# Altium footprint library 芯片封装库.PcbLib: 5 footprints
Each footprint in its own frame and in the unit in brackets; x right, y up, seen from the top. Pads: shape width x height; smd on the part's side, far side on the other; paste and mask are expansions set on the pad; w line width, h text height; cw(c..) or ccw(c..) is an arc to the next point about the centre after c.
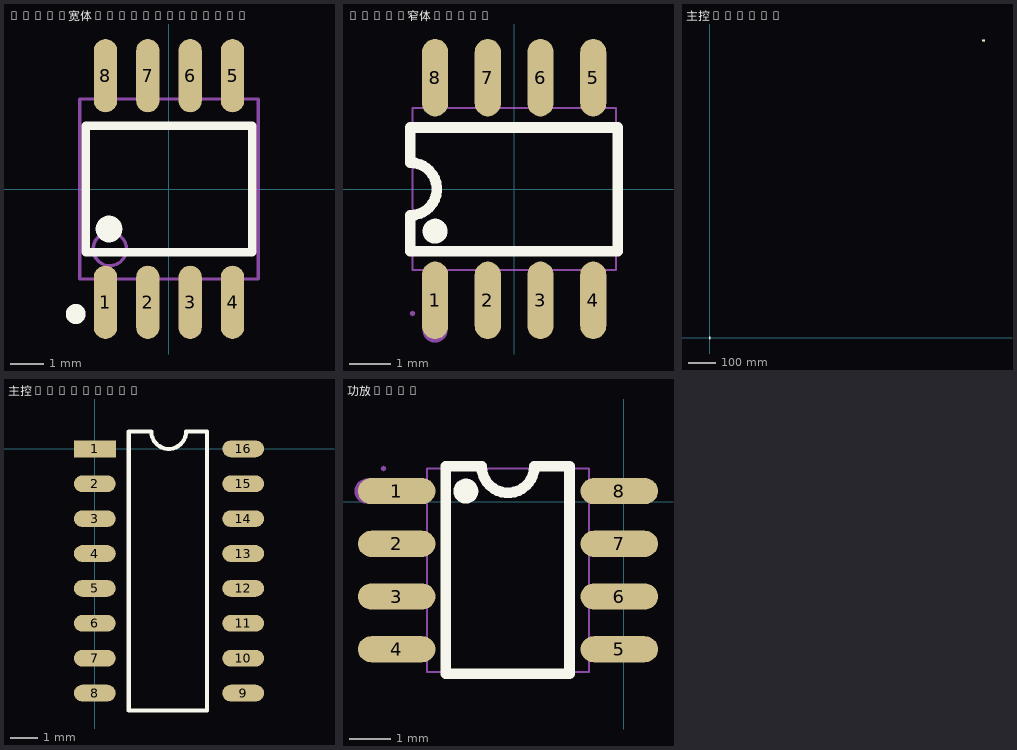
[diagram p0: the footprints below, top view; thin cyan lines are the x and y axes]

## flash宽体SOIC-8_208mil [mm]
height 5.33
pads (8):
  oval 0.7x2.2 smd: 1(-1.905,-3.4) 2(-0.635,-3.4) 3(0.635,-3.4) 4(1.905,-3.4) 5(1.905,3.4) 6(0.635,3.4) 7(-0.635,3.4) 8(-1.905,3.4)
Top Overlay:
  circle w0.4: c-1.8,-1.2 r0.2
  circle w0.3: c-2.797,-3.75 r0.15
  lines w0.254: -2.5,-1.9 2.5,-1.9 2.5,1.9 -2.5,1.9 -2.5,-1.9
Mechanical 13:
  circle w0.1: c-1.775,-1.8 r0.5
  lines w0.1: -2.675,-2.7 2.675,-2.7 2.675,2.7 -2.675,2.7 -2.675,-2.7

## flash窄体SOP-8 [mm]
pads (8):
  oval 0.63x1.865 smd: 1(-1.905,-2.682) 2(-0.635,-2.682) 3(0.635,-2.682) 4(1.905,-2.682) 5(1.905,2.682) 6(0.635,2.682) 7(-0.635,2.682) 8(-1.905,2.682)
Top Overlay:
  circle w0.3: c-1.905,-1.016 r0.15
  lines w0.254: -2.5,-1.498 -2.5,-0.635 ccw(c-2.5,0) -2.499,0.635 -2.499,1.482 2.5,1.482 2.5,-1.498 -2.5,-1.498
Mechanical 6:
  circle w0.3: c-1.905,-3.4 r0.15
Mechanical 15:
  region: -2.385,-3 -2.404,-2.954 -2.45,-2.935 -2.496,-2.954 -2.515,-3 -2.496,-3.046 -2.45,-3.065 -2.404,-3.046 -2.385,-3
  region: 1.695,2.165 1.695,3 2.115,3 2.115,2.165
  region: 0.425,2.165 0.425,3 0.845,3 0.845,2.165
  region: -0.845,2.165 -0.845,3 -0.425,3 -0.425,2.165
  region: -2.115,2.165 -2.115,3 -1.695,3 -1.695,2.165
  region: 1.695,-3 1.695,-2.165 2.115,-2.165 2.115,-3
  region: 0.425,-3 0.425,-2.165 0.845,-2.165 0.845,-3
  region: -0.845,-3 -0.845,-2.165 -0.425,-2.165 -0.425,-3
  region: -2.115,-3 -2.115,-2.165 -1.695,-2.165 -1.695,-3
  region: 1.695,2.232 2.115,2.232 2.115,1.942 1.695,1.942
  region: 0.425,2.232 0.845,2.232 0.845,1.942 0.425,1.942
  region: -0.845,2.232 -0.425,2.232 -0.425,1.942 -0.845,1.942
  region: -2.115,2.232 -1.695,2.232 -1.695,1.942 -2.115,1.942
  region: -1.695,-2.232 -2.115,-2.232 -2.115,-1.942 -1.695,-1.942
  region: -0.425,-2.232 -0.845,-2.232 -0.845,-1.942 -0.425,-1.942
  region: 0.845,-2.232 0.425,-2.232 0.425,-1.942 0.845,-1.942
  region: 2.115,-2.232 1.695,-2.232 1.695,-1.942 2.115,-1.942
  lines w0.051: -2.45,-1.95 -2.45,1.95 2.45,1.95 2.45,-1.95 -2.45,-1.95

## 主控QSOP24 [mil]
pads (48):
  rect 59.06x12.99 smd: 1(-122.05,137.5) 24(122.05,137.5)
  rect 13x65 smd: 1(39800.51,43285.81) 2(39826.1,43285.81) 3(39851.69,43285.81) 4(39877.28,43285.81) 5(39902.87,43285.81) 6(39928.46,43285.81) 7(39954.06,43285.81) 8(39979.65,43285.81) 9(40005.24,43285.81) 10(40030.83,43285.81) 11(40056.42,43285.81) 12(40082.01,43285.81) 13(40082.01,43545.81) 14(40056.42,43545.81) 15(40030.83,43545.81) 16(40005.24,43545.81) 17(39979.65,43545.81) 18(39954.06,43545.81) 19(39928.46,43545.81) 20(39902.87,43545.81) 21(39877.28,43545.81) 22(39851.69,43545.81) 23(39826.1,43545.81) 24(39800.51,43545.81)
  oval 59.06x12.99 smd: 2(-122.05,112.5) 3(-122.05,87.5) 4(-122.05,62.5) 5(-122.05,37.5) 6(-122.05,12.5) 7(-122.05,-12.5) 8(-122.05,-37.5) 9(-122.05,-62.5) 10(-122.05,-87.5) 11(-122.05,-112.5) 12(-122.05,-137.5) 13(122.05,-137.5) 14(122.05,-112.5) 15(122.05,-87.5) 16(122.05,-62.5) 17(122.05,-37.5) 18(122.05,-12.5) 19(122.05,12.5) 20(122.05,37.5) 21(122.05,62.5) 22(122.05,87.5) 23(122.05,112.5)
Top Overlay:
  circle w7.87: c39803.81,43360.81 r12.45
  lines w7.87: -68.45,-170.43 -68.45,170.51 -21.2,170.51 ccw(c0,170.47) 21.2,170.51 68.45,170.51 68.45,-170.43 -68.45,-170.43
  lines w10: 39779.84,43335.81 39941.26,43335.81 40102.68,43335.81 40102.68,43495.81 39941.26,43495.81 39779.84,43495.81 39779.84,43437.23 cw(c39781.26,43415.81) 39779.84,43394.39 39779.84,43335.81

## 主控SOP-16PIN [mil]
pads (16):
  rect 60x24 smd: 1(0,0)
  oval 60x24 smd: 2(0,-50) 3(0,-100) 4(0,-150) 5(0,-200) 6(0,-250) 7(0,-300) 8(0,-350) 9(212.6,-350) 10(212.6,-300) 11(212.6,-250) 12(212.6,-200) 13(212.6,-150) 14(212.6,-100) 15(212.6,-50) 16(212.6,0)
Top Overlay:
  lines w5.91: 48.58,-375 160.79,-375 160.79,25 130.87,25 cw(c105.87,25) 80.87,25 48.58,25 48.58,-375

## 功放SOP8 [mm]
pads (8):
  oval 1.865x0.63 smd: 1(-5.476,0.254) 2(-5.476,-1.016) 3(-5.476,-2.286) 4(-5.476,-3.556) 5(-0.112,-3.556) 6(-0.112,-2.286) 7(-0.112,-1.016) 8(-0.112,0.254)
Top Overlay:
  circle w0.3: c-3.81,0.254 r0.15
  lines w0.254: -4.292,-4.151 -4.292,0.849 -3.429,0.849 ccw(c-2.794,0.849) -2.159,0.848 -1.312,0.848 -1.312,-4.151 -4.292,-4.151
Mechanical 6:
  circle w0.3: c-6.194,0.254 r0.15
Mechanical 15:
  region: -5.026,-3.766 -5.026,-3.346 -4.736,-3.346 -4.736,-3.766
  region: -5.026,-2.496 -5.026,-2.076 -4.736,-2.076 -4.736,-2.496
  region: -5.026,-1.226 -5.026,-0.806 -4.736,-0.806 -4.736,-1.226
  region: -5.026,0.044 -5.026,0.464 -4.736,0.464 -4.736,0.044
  region: -0.562,0.464 -0.562,0.044 -0.852,0.044 -0.852,0.464
  region: -0.562,-0.806 -0.562,-1.226 -0.852,-1.226 -0.852,-0.806
  region: -0.562,-2.076 -0.562,-2.496 -0.852,-2.496 -0.852,-2.076
  region: -0.562,-3.346 -0.562,-3.766 -0.852,-3.766 -0.852,-3.346
  region: -5.794,0.464 -4.959,0.464 -4.959,0.044 -5.794,0.044
  region: -5.794,-0.806 -4.959,-0.806 -4.959,-1.226 -5.794,-1.226
  region: -5.794,-2.076 -4.959,-2.076 -4.959,-2.496 -5.794,-2.496
  region: -5.794,-3.346 -4.959,-3.346 -4.959,-3.766 -5.794,-3.766
  region: -0.629,0.464 0.206,0.464 0.206,0.044 -0.629,0.044
  region: -0.629,-0.806 0.206,-0.806 0.206,-1.226 -0.629,-1.226
  region: -0.629,-2.076 0.206,-2.076 0.206,-2.496 -0.629,-2.496
  region: -0.629,-3.346 0.206,-3.346 0.206,-3.766 -0.629,-3.766
  region: -5.794,0.734 -5.748,0.753 -5.729,0.799 -5.748,0.845 -5.794,0.864 -5.84,0.845 -5.859,0.799 -5.84,0.753 -5.794,0.734
  lines w0.051: -4.744,-4.101 -4.744,0.799 -0.844,0.799 -0.844,-4.101 -4.744,-4.101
